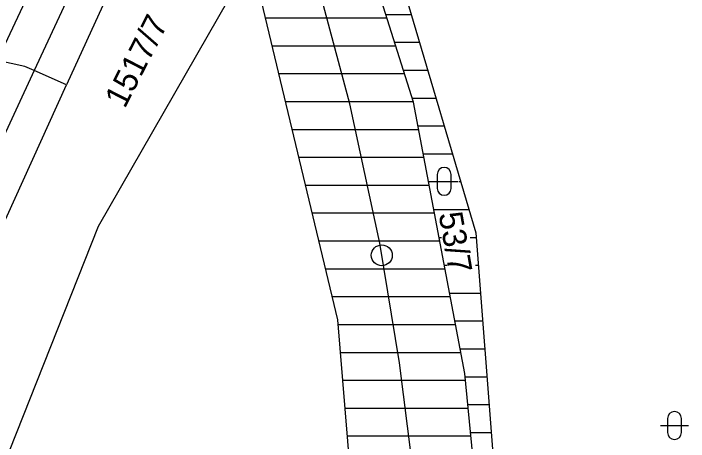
# Model space of a CAD drawing. Extents: x -553916 to -552953, y -1067470 to -1066637.
# Drawn here: x -553532.46 to -553484.03, y -1067025.62 to -1066994.91 of the extents above; entities that cross this region are included whole.
import ezdxf

# ---------------------------------------------------------------- set-up
doc = ezdxf.new("R2010")
doc.units = 0
for name, color, linetype in [('Hranice parcel', 7, 'Continuous'), ('Kolej', 7, 'Continuous'), ('Návěst místo trati', 7, 'Continuous'), ('Parcelní čísla', 7, 'Continuous'), ('Propustek', 7, 'Continuous'), ('Vrstva 1', 7, 'Continuous'), ('Značky kultur', 7, 'Continuous')]:
    doc.layers.add(name, color=color, linetype=linetype)

msp = doc.modelspace()

# ---------------------------------------------------------------- linework, layer by layer
at = {"layer": 'Hranice parcel'}
for p, q in [((-553520.52, -1066976.45), (-553530.98, -1066998.99)), ((-553519.4, -1066979.7), (-553528.66, -1067000.03)), ((-553530.98, -1066998.99), (-553538.9, -1067016.05)), ((-553528.66, -1067000.03), (-553530.98, -1066998.99)), ((-553535.85, -1067015.85), (-553528.66, -1067000.03))]:
    msp.add_line(p, q, dxfattribs=at)
for points in [[(-553533.63, -1066998.28), (-553526.12, -1066982.3), (-553521.68, -1066973.05)], [(-553515.43, -1066991.08), (-553526.38, -1067010.19), (-553539.65, -1067043.59), (-553548.33, -1067069.03)], [(-553530.98, -1066998.99), (-553531.64, -1066998.7), (-553533.63, -1066998.28)]]:
    msp.add_lwpolyline(points, dxfattribs=at)
at = {"layer": 'Kolej'}
msp.add_lwpolyline([(-553503.324, -1067065.808), (-553502.678, -1067054.027), (-553502.762, -1067041.504), (-553503.626, -1067029.057), (-553504.756, -1067019.974), (-553506.183, -1067011.388), (-553508.328, -1067001.388), (-553510.948, -1066991.622), (-553512.921, -1066985.291), (-553515.647, -1066977.347), (-553517.422, -1066972.53), (-553519.157, -1066967.95), (-553522.886, -1066958.375), (-553529.101, -1066942.549), (-553538.686, -1066918.107), (-553542.908, -1066907.329), (-553546.692, -1066897.676), (-553555.025, -1066876.441), (-553564.644, -1066851.894), (-553574.241, -1066827.427), (-553583.19, -1066804.618)], dxfattribs=at)
at = {"layer": 'Návěst místo trati'}
msp.add_circle((-553506.038, -1067012.26), 0.75, dxfattribs=at)
at = {"layer": 'Propustek'}
for p, q in [((-553505.83, -1066988.51), (-553499.28, -1067010.65)), ((-553505.749, -1066994.97), (-553503.919, -1066994.97)), ((-553514.374, -1066995.222), (-553505.67, -1066995.222)), ((-553505.121, -1066996.97), (-553503.327, -1066996.97)), ((-553513.895, -1066997.222), (-553505.042, -1066997.222)), ((-553513.415, -1066999.222), (-553504.415, -1066999.222)), ((-553504.494, -1066998.97), (-553502.735, -1066998.97)), ((-553512.936, -1067001.222), (-553503.788, -1067001.222)), ((-553503.867, -1067000.97), (-553502.144, -1067000.97)), ((-553512.457, -1067003.222), (-553503.402, -1067003.222)), ((-553503.449, -1067002.97), (-553501.552, -1067002.97)), ((-553503.07, -1067004.97), (-553500.96, -1067004.97)), ((-553511.978, -1067005.222), (-553503.022, -1067005.222)), ((-553502.691, -1067006.97), (-553502.584, -1067006.97)), ((-553500.49, -1067006.97), (-553500.369, -1067006.97)), ((-553511.499, -1067007.222), (-553502.643, -1067007.222)), ((-553502.311, -1067008.97), (-553499.777, -1067008.97)), ((-553511.02, -1067009.222), (-553502.263, -1067009.222)), ((-553501.932, -1067010.97), (-553501.762, -1067010.97)), ((-553499.692, -1067010.97), (-553499.255, -1067010.97)), ((-553499.28, -1067010.65), (-553496.78, -1067043.02)), ((-553510.54, -1067011.222), (-553501.884, -1067011.222)), ((-553510.061, -1067013.222), (-553501.504, -1067013.222)), ((-553501.552, -1067012.97), (-553501.355, -1067012.97)), ((-553499.323, -1067012.97), (-553499.101, -1067012.97)), ((-553509.582, -1067015.222), (-553501.125, -1067015.222)), ((-553501.173, -1067014.97), (-553498.946, -1067014.97)), ((-553509.153, -1067017.222), (-553500.746, -1067017.222)), ((-553500.793, -1067016.97), (-553498.792, -1067016.97)), ((-553508.989, -1067019.222), (-553500.366, -1067019.222)), ((-553500.414, -1067018.97), (-553498.637, -1067018.97)), ((-553500.057, -1067020.97), (-553498.483, -1067020.97)), ((-553508.824, -1067021.222), (-553500.032, -1067021.222)), ((-553499.863, -1067022.97), (-553498.329, -1067022.97)), ((-553508.659, -1067023.222), (-553499.838, -1067023.222)), ((-553499.669, -1067024.97), (-553498.174, -1067024.97)), ((-553508.494, -1067025.222), (-553499.644, -1067025.222))]:
    msp.add_line(p, q, dxfattribs=at)
for points in [[(-553498.68, -1067074.42), (-553498.17, -1067040.43), (-553500.08, -1067020.73), (-553503.77, -1067001.28), (-553507.63, -1066988.97), (-553505.83, -1066988.51)], [(-553509.03, -1067072.35), (-553507.22, -1067040.68), (-553509.18, -1067016.9), (-553515.22, -1066991.69), (-553515.43, -1066991.08)]]:
    msp.add_lwpolyline(points, dxfattribs=at)
at = {"layer": 'Značky kultur'}
for p, q in [((-553502.06, -1067006.453), (-553502.06, -1067007.454)), ((-553501.058, -1067007.454), (-553501.058, -1067006.453)), ((-553502.56, -1067006.953), (-553500.558, -1067006.953)), ((-553485.531, -1067023.971), (-553485.531, -1067024.972)), ((-553484.529, -1067024.972), (-553484.529, -1067023.971)), ((-553486.031, -1067024.471), (-553484.029, -1067024.471))]:
    msp.add_line(p, q, dxfattribs=at)
for centre, start, end in [((-553501.559, -1067006.453), 0, 180), ((-553501.559, -1067007.453), 180, 359.9879), ((-553485.03, -1067023.971), 0, 180), ((-553485.03, -1067024.971), 180, 359.9879)]:
    msp.add_arc(centre, 0.5, start, end, dxfattribs=at)

# ---------------------------------------------------------------- texts
at = {"layer": 'Parcelní čísla'}
msp.add_text('1517/7', height=1.7, rotation=63, dxfattribs=at).set_placement((-553524.481, -1067001.782))
at = {"layer": 'Vrstva 1'}
msp.add_text('53/7', height=1.7, rotation=280, dxfattribs=at).set_placement((-553501.965, -1067009.286))

doc.saveas('drawing.dxf')
